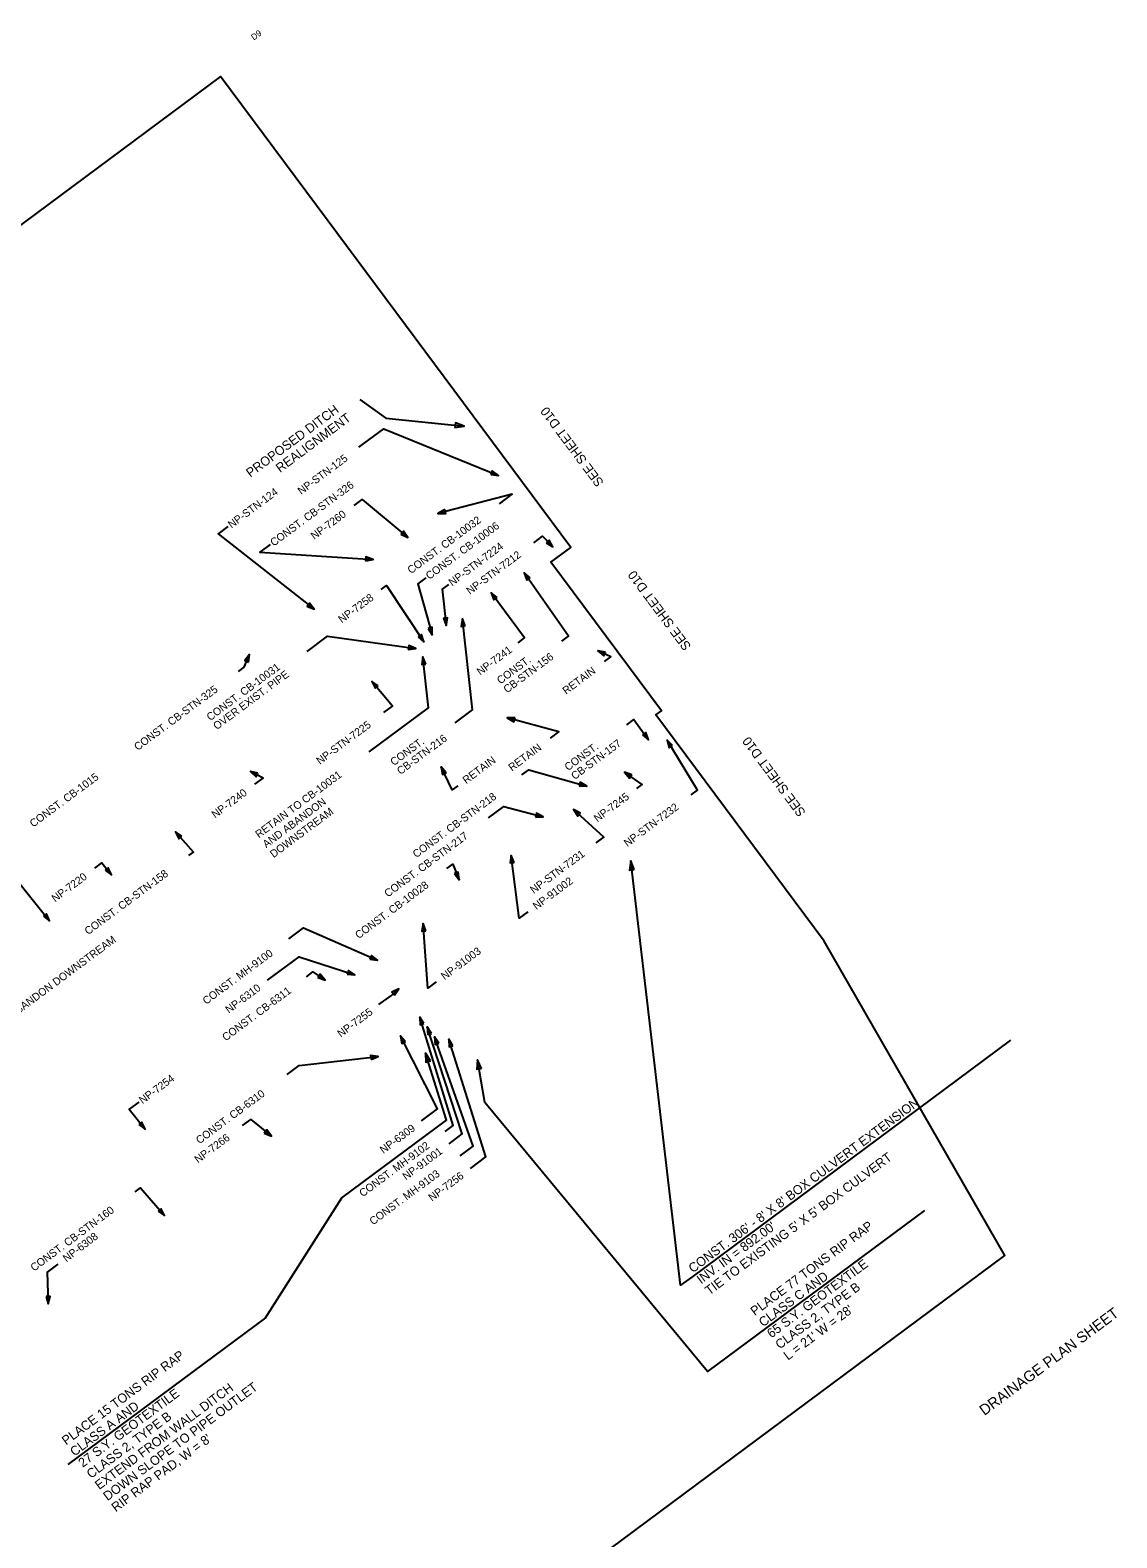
# Model space of a CAD drawing. Extents: x 1612334 to 1614149, y 1094755 to 1096548.
# Drawn here: x 1613444 to 1614149, y 1095569 to 1096548 of the extents above; entities that cross this region are included whole.
import ezdxf

# ---------------------------------------------------------------- set-up
doc = ezdxf.new("R2010")
doc.units = 0
for name, color, linetype in [('Level 13', 7, 'Continuous'), ('Level 15', 7, 'Continuous'), ('Level 9', 7, 'Continuous'), ('Node Storage', 7, 'Continuous'), ('RD_HY_DumbNodes', 7, 'Continuous')]:
    doc.layers.add(name, color=color, linetype=linetype)

msp = doc.modelspace()

# ---------------------------------------------------------------- linework, layer by layer
at = {"layer": 'Level 15'}
msp.add_lwpolyline([(1612485.6, 1095458.44), (1612588.44, 1095320.1), (1612593.04, 1095313.91), (1612580.15, 1095304.29), (1612634.52, 1095231.15), (1612645.51, 1095216.31), (1612653.41, 1095198.54), (1612742.51, 1095078.69), (1612867.99, 1094853.86), (1614076.24, 1095752.03), (1613959.14, 1095956.14), (1613849.89, 1096103.11), (1613853.42, 1096105.74), (1613781.72, 1096202.21), (1613794.63, 1096211.8), (1613636.52, 1096424.5), (1613567.38, 1096517.5), (1613431.61, 1096416.58), (1613412.2, 1096442.69), (1612334.44, 1095641.53)], close=True, dxfattribs=at)
msp.add_lwpolyline([(1612485.6, 1095458.44), (1612588.44, 1095320.1), (1612593.04, 1095313.91), (1612580.15, 1095304.29), (1612634.52, 1095231.15), (1612645.51, 1095216.31), (1612653.41, 1095198.54), (1612742.51, 1095078.69), (1612867.99, 1094853.86), (1614076.24, 1095752.03), (1613959.14, 1095956.14), (1613849.89, 1096103.11), (1613853.42, 1096105.74), (1613781.72, 1096202.21), (1613794.63, 1096211.8), (1613636.52, 1096424.5), (1613567.38, 1096517.5), (1613431.61, 1096416.58), (1613412.2, 1096442.69), (1612334.44, 1095641.53)], close=True, dxfattribs=at)
msp.add_lwpolyline([(1612485.6, 1095458.44), (1612588.44, 1095320.1), (1612593.04, 1095313.91), (1612580.15, 1095304.29), (1612634.52, 1095231.15), (1612645.51, 1095216.31), (1612653.41, 1095198.54), (1612742.51, 1095078.69), (1612867.99, 1094853.86), (1614076.24, 1095752.03), (1613959.14, 1095956.14), (1613849.89, 1096103.11), (1613853.42, 1096105.74), (1613781.72, 1096202.21), (1613794.63, 1096211.8), (1613636.52, 1096424.5), (1613567.38, 1096517.5), (1613431.61, 1096416.58), (1613412.2, 1096442.69), (1612334.44, 1095641.53)], close=True, dxfattribs=at)
msp.add_lwpolyline([(1612485.6, 1095458.44), (1612588.44, 1095320.1), (1612593.04, 1095313.91), (1612580.15, 1095304.29), (1612634.52, 1095231.15), (1612645.51, 1095216.31), (1612653.41, 1095198.54), (1612742.51, 1095078.69), (1612867.99, 1094853.86), (1614076.24, 1095752.03), (1613959.14, 1095956.14), (1613849.89, 1096103.11), (1613853.42, 1096105.74), (1613781.72, 1096202.21), (1613794.63, 1096211.8), (1613636.52, 1096424.5), (1613567.38, 1096517.5), (1613431.61, 1096416.58), (1613412.2, 1096442.69), (1612334.44, 1095641.53)], close=True, dxfattribs=at)
msp.add_lwpolyline([(1612485.6, 1095458.44), (1612588.44, 1095320.1), (1612593.04, 1095313.91), (1612580.15, 1095304.29), (1612634.52, 1095231.15), (1612645.51, 1095216.31), (1612653.41, 1095198.54), (1612742.51, 1095078.69), (1612867.99, 1094853.86), (1614076.24, 1095752.03), (1613959.14, 1095956.14), (1613849.89, 1096103.11), (1613853.42, 1096105.74), (1613781.72, 1096202.21), (1613794.63, 1096211.8), (1613636.52, 1096424.5), (1613567.38, 1096517.5), (1613431.61, 1096416.58), (1613412.2, 1096442.69), (1612334.44, 1095641.53)], close=True, dxfattribs=at)
msp.add_lwpolyline([(1612485.6, 1095458.44), (1612588.44, 1095320.1), (1612593.04, 1095313.91), (1612580.15, 1095304.29), (1612634.52, 1095231.15), (1612645.51, 1095216.31), (1612653.41, 1095198.54), (1612742.51, 1095078.69), (1612867.99, 1094853.86), (1614076.24, 1095752.03), (1613959.14, 1095956.14), (1613849.89, 1096103.11), (1613853.42, 1096105.74), (1613781.72, 1096202.21), (1613794.63, 1096211.8), (1613636.52, 1096424.5), (1613567.38, 1096517.5), (1613431.61, 1096416.58), (1613412.2, 1096442.69), (1612334.44, 1095641.53)], close=True, dxfattribs=at)
msp.add_lwpolyline([(1612485.6, 1095458.44), (1612588.44, 1095320.1), (1612593.04, 1095313.91), (1612580.15, 1095304.29), (1612634.52, 1095231.15), (1612645.51, 1095216.31), (1612653.41, 1095198.54), (1612742.51, 1095078.69), (1612867.99, 1094853.86), (1614076.24, 1095752.03), (1613959.14, 1095956.14), (1613849.89, 1096103.11), (1613853.42, 1096105.74), (1613781.72, 1096202.21), (1613794.63, 1096211.8), (1613636.52, 1096424.5), (1613567.38, 1096517.5), (1613431.61, 1096416.58), (1613412.2, 1096442.69), (1612334.44, 1095641.53)], close=True, dxfattribs=at)
msp.add_lwpolyline([(1612485.6, 1095458.44), (1612588.44, 1095320.1), (1612593.04, 1095313.91), (1612580.15, 1095304.29), (1612634.52, 1095231.15), (1612645.51, 1095216.31), (1612653.41, 1095198.54), (1612742.51, 1095078.69), (1612867.99, 1094853.86), (1614076.24, 1095752.03), (1613959.14, 1095956.14), (1613849.89, 1096103.11), (1613853.42, 1096105.74), (1613781.72, 1096202.21), (1613794.63, 1096211.8), (1613636.52, 1096424.5), (1613567.38, 1096517.5), (1613431.61, 1096416.58), (1613412.2, 1096442.69), (1612334.44, 1095641.53)], close=True, dxfattribs=at)
at = {"layer": 'RD_HY_DumbNodes'}
for p, q in [((1614080, 1095891.94), (1613873.1, 1095738.15)), ((1614024.06, 1095781.42), (1613915.13, 1095700.45)), ((1613596.48, 1095711.77), (1613468.24, 1095616.45))]:
    msp.add_line(p, q, dxfattribs=at)
for points in [[(1613657.71, 1096307.85), (1613674.6, 1096295.74), (1613725.35, 1096290.5)], [(1613657.18, 1096276.77), (1613673.38, 1096288.82), (1613747.68, 1096258.44)], [(1613654.01, 1096238.95), (1613659.32, 1096242.9), (1613688.88, 1096218.28)], [(1613748.34, 1096240.15), (1613756.61, 1096246.3), (1613708.44, 1096233.88)], [(1613572.19, 1096225.38), (1613565.78, 1096220.61), (1613628.01, 1096171.71)], [(1613599.6, 1096213.66), (1613592.87, 1096208.65), (1613666.29, 1096203.99)], [(1613770.62, 1096214.85), (1613776.37, 1096219.12), (1613782.99, 1096212.21)], [(1613700.53, 1096192.05), (1613695.4, 1096188.24), (1613704.71, 1096154.94)], [(1613788.77, 1096150.99), (1613793.05, 1096154.17), (1613764.43, 1096195.29)], [(1613671.56, 1096184.53), (1613675.04, 1096187.12), (1613699.37, 1096150.51)], [(1613715.37, 1096187.81), (1613711.22, 1096184.73), (1613713.76, 1096161.21)], [(1613760.4, 1096149.87), (1613764.62, 1096153.01), (1613742.87, 1096182.39)], [(1613719.66, 1096098.01), (1613730.79, 1096106.28), (1613724.3, 1096165.47)], [(1613623.5, 1096144.28), (1613636.83, 1096154.19), (1613694.04, 1096146.09)], [(1613816.53, 1096137.76), (1613820.53, 1096140.74), (1613812.23, 1096144.74)], [(1613578.94, 1096131.29), (1613582.65, 1096134.05), (1613586.21, 1096142.34)], [(1613663.77, 1096079.15), (1613702.21, 1096107.72), (1613698.7, 1096140.74)], [(1613673.27, 1096104.53), (1613679.01, 1096108.8), (1613665.49, 1096124.86)], [(1613781.4, 1096087.9), (1613786.94, 1096092.02), (1613753.43, 1096101.13)], [(1613831, 1096096.58), (1613835.59, 1096099.99), (1613845, 1096086.91)], [(1613872.83, 1096051.11), (1613876.95, 1096054.17), (1613857.11, 1096086.57)], [(1613589.71, 1096058.1), (1613595.03, 1096062.05), (1613586.78, 1096066.35)], [(1613721.25, 1096057.04), (1613717.62, 1096054.35), (1613710.51, 1096069.27)], [(1613762.94, 1096064.09), (1613767.31, 1096067.33), (1613805.02, 1096056.88)], [(1613837.42, 1096055.33), (1613840.94, 1096057.95), (1613829.48, 1096065.88)], [(1613741.29, 1096036.15), (1613751.18, 1096043.5), (1613776.71, 1096036.8)], [(1613811, 1096019.96), (1613816.05, 1096023.72), (1613796.42, 1096041.63)], [(1613546.77, 1096011.7), (1613549.86, 1096014), (1613538.11, 1096027.06)], [(1613485.89, 1096003.62), (1613490.41, 1096006.98), (1613496.5, 1095999.22)], [(1613714.22, 1096003.39), (1613718.07, 1096006.25), (1613722.25, 1095996.06)], [(1613766.84, 1095975.27), (1613761.17, 1095971.06), (1613755.96, 1096011.9)], [(1613873.1, 1095738.15), (1613865.87, 1095732.78), (1613833.55, 1096008.29)], [(1613428.12, 1095991.63), (1613434.7, 1095996.53), (1613456.39, 1095969.37)], [(1613707.26, 1095929.78), (1613701.84, 1095925.75), (1613698.85, 1095967.56)], [(1613611.57, 1095957.66), (1613621.21, 1095964.83), (1613669.26, 1095943.81)], [(1613597.84, 1095930.8), (1613618.43, 1095946.12), (1613654.53, 1095934.43)], [(1613623.12, 1095933.14), (1613627.3, 1095936.25), (1613635.2, 1095930.96)], [(1613670.16, 1095914.98), (1613678.24, 1095920.98), (1613682.98, 1095925.35)], [(1613713.07, 1095832.68), (1613718.33, 1095836.59), (1613696.7, 1095906.9)], [(1613715.71, 1095824.73), (1613724.17, 1095831.02), (1613701.51, 1095900.5)], [(1613697.76, 1095839.51), (1613708.16, 1095847.24), (1613684.06, 1095894.7)], [(1613722.93, 1095816.82), (1613731.25, 1095823.01), (1613706.25, 1095894.06)], [(1613729.46, 1095808.71), (1613739.52, 1095816.19), (1613715.42, 1095892.56)], [(1613596.48, 1095711.77), (1613645.98, 1095789.48), (1613714.05, 1095840.07), (1613700.41, 1095883.55)], [(1613610.6, 1095869.68), (1613618.33, 1095875.42), (1613669.69, 1095881.21)], [(1613915.13, 1095700.45), (1613883.42, 1095676.87), (1613738.81, 1095851.48), (1613734.2, 1095879.08)], [(1613514.44, 1095851.69), (1613508.15, 1095847.02), (1613518.38, 1095834.12)], [(1613581.67, 1095836.45), (1613586.98, 1095840.41), (1613600.32, 1095829.62)], [(1613512.01, 1095793.49), (1613515.35, 1095795.98), (1613530.96, 1095778.02)], [(1613461.88, 1095746.56), (1613454.94, 1095741.28), (1613455.56, 1095720.68)]]:
    msp.add_lwpolyline(points, dxfattribs=at)
for points in [[(1613719.43, 1096289.55), (1613725.35, 1096290.5), (1613719.75, 1096292.64)], [(1613742.72, 1096259.07), (1613747.68, 1096258.44), (1613743.7, 1096261.47)], [(1613712.79, 1096236.33), (1613708.44, 1096233.88), (1613713.44, 1096233.83)], [(1613684.35, 1096220.37), (1613688.88, 1096218.28), (1613686, 1096222.36)], [(1613778.72, 1096214.8), (1613782.99, 1096212.21), (1613780.58, 1096216.59)], [(1613661.38, 1096203.01), (1613666.29, 1096203.99), (1613661.55, 1096205.59)], [(1613768.25, 1096192.07), (1613764.43, 1096195.29), (1613766.12, 1096190.59)], [(1613746.79, 1096179.28), (1613742.87, 1096182.39), (1613744.71, 1096177.73)], [(1613623.41, 1096173.67), (1613628.01, 1096171.71), (1613625.01, 1096175.71)], [(1613711.95, 1096165.87), (1613713.76, 1096161.21), (1613714.53, 1096166.15)], [(1613726.11, 1096160.81), (1613724.3, 1096165.47), (1613723.54, 1096160.52)], [(1613695.62, 1096153.82), (1613699.37, 1096150.51), (1613697.78, 1096155.25)], [(1613702.16, 1096159.25), (1613704.71, 1096154.94), (1613704.65, 1096159.94)], [(1613689.08, 1096145.48), (1613694.04, 1096146.09), (1613689.44, 1096148.05)], [(1613817.14, 1096143.81), (1613812.23, 1096144.74), (1613816.02, 1096141.48)], [(1613585.5, 1096137.4), (1613586.21, 1096142.34), (1613583.12, 1096138.42)], [(1613700.5, 1096136.08), (1613698.7, 1096140.74), (1613697.92, 1096135.8)], [(1613669.59, 1096122), (1613665.49, 1096124.86), (1613667.61, 1096120.33)], [(1613758.43, 1096101.12), (1613753.43, 1096101.13), (1613757.75, 1096098.62)], [(1613841.13, 1096090.08), (1613845, 1096086.91), (1613843.23, 1096091.59)], [(1613860.73, 1096083.12), (1613857.11, 1096086.57), (1613858.52, 1096081.77)], [(1613591.66, 1096065.27), (1613586.78, 1096066.35), (1613590.46, 1096062.97)], [(1613713.75, 1096065.46), (1613710.51, 1096069.27), (1613711.42, 1096064.35)], [(1613834.19, 1096064.2), (1613829.48, 1096065.88), (1613832.72, 1096062.07)], [(1613800.02, 1096056.92), (1613805.02, 1096056.88), (1613800.71, 1096059.42)], [(1613771.71, 1096036.78), (1613776.71, 1096036.8), (1613772.36, 1096039.28)], [(1613800.86, 1096039.33), (1613796.42, 1096041.63), (1613799.12, 1096037.42)], [(1613542.3, 1096024.33), (1613538.11, 1096027.06), (1613540.38, 1096022.6)], [(1613757.85, 1096007.28), (1613755.96, 1096011.9), (1613755.29, 1096006.95)], [(1613835.77, 1096002.71), (1613833.55, 1096008.29), (1613832.69, 1096002.35)], [(1613492.5, 1096002.22), (1613496.5, 1095999.22), (1613494.54, 1096003.81)], [(1613719.22, 1096000.04), (1613722.25, 1095996.06), (1613721.61, 1096001.02)], [(1613452.37, 1095972.33), (1613456.39, 1095969.37), (1613454.39, 1095973.95)], [(1613700.48, 1095962.84), (1613698.85, 1095967.56), (1613697.9, 1095962.65)], [(1613664.31, 1095944.56), (1613669.26, 1095943.81), (1613665.35, 1095946.93)], [(1613649.54, 1095934.68), (1613654.53, 1095934.43), (1613650.34, 1095937.14)], [(1613630.47, 1095932.57), (1613635.2, 1095930.96), (1613631.91, 1095934.72)], [(1613680.31, 1095921.13), (1613682.98, 1095925.35), (1613678.55, 1095923.03)], [(1613699.36, 1095902.66), (1613696.7, 1095906.9), (1613696.88, 1095901.9)], [(1613704.24, 1095896.31), (1613701.51, 1095900.5), (1613701.78, 1095895.51)], [(1613687.4, 1095890.98), (1613684.06, 1095894.7), (1613685.1, 1095889.81)], [(1613709.07, 1095889.93), (1613706.25, 1095894.06), (1613706.63, 1095889.07)], [(1613718.11, 1095888.34), (1613715.42, 1095892.56), (1613715.64, 1095887.56)], [(1613665.04, 1095879.38), (1613669.69, 1095881.21), (1613664.75, 1095881.96)], [(1613703.62, 1095878.48), (1613700.41, 1095883.55), (1613700.66, 1095877.55)], [(1613736.69, 1095873.62), (1613734.2, 1095879.08), (1613733.62, 1095873.11)], [(1613514.36, 1095837.1), (1613518.38, 1095834.12), (1613516.39, 1095838.71)], [(1613595.75, 1095831.65), (1613600.32, 1095829.62), (1613597.38, 1095833.66)], [(1613526.81, 1095780.82), (1613530.96, 1095778.02), (1613528.77, 1095782.52)], [(1613454.12, 1095725.47), (1613455.56, 1095720.68), (1613456.71, 1095725.54)]]:
    msp.add_lwpolyline(points, close=True, dxfattribs=at)

# ---------------------------------------------------------------- texts
at = {"layer": 'Level 13'}
for p in [(1613816.33, 1096253.99), (1613873.03, 1096147.7), (1613947.35, 1096039.81)]:
    msp.add_text('SEE SHEET D10', height=6, rotation=126.67686, dxfattribs=at).set_placement(p)
at = {"layer": 'Level 9'}
msp.add_text('D9', height=4, rotation=36.62559, dxfattribs=at).set_placement((1613588.95, 1096540.78))
at = {"layer": 'Node Storage'}
msp.add_text('DRAINAGE PLAN SHEET', height=6.9833, rotation=36.62559, dxfattribs=at).set_placement((1614063.02, 1095647.9))
at = {"layer": 'RD_HY_DumbNodes'}
for s, height, rotation, p in [('PROPOSED DITCH', 6, 36.62397, (1613586.72, 1096256.95)), ('REALIGNMENT', 6, 36.62397, (1613606.01, 1096260.07)), ('NP-STN-125', 5, 36.62397, (1613619.7, 1096245.8)), ('NP-STN-124', 5, 36.62397, (1613574.48, 1096223.97)), ('CONST. CB-STN-326', 5, 36.62397, (1613601.9, 1096212.25)), ('NP-7260', 5, 36.62397, (1613628.16, 1096216.61)), ('CONST. CB-10032', 5, 36.62397, (1613690.95, 1096194.38)), ('CONST. CB-10006', 5, 36.62397, (1613702.83, 1096190.64)), ('NP-STN-7224', 5, 36.62397, (1613717.66, 1096186.4)), ('NP-STN-7212', 5, 36.62397, (1613729.16, 1096180.92)), ('NP-7258', 5, 36.62397, (1613646.02, 1096162.44)), ('NP-7241', 5, 36.62397, (1613735.88, 1096128.53)), ('CB-STN-156', 5, 36.62397, (1613753.25, 1096116.98)), ('CONST. CB-10031', 5, 36.62397, (1613560.62, 1096098.92)), ('CONST.', 5, 36.62397, (1613748.95, 1096122.76)), ('RETAIN', 5, 36.62397, (1613791.57, 1096116.09)), ('OVER EXIST. PIPE', 5, 36.62397, (1613564.92, 1096093.13)), ('CONST. CB-STN-325', 5, 36.62397, (1613513.59, 1096079.6)), ('NP-STN-7225', 5, 36.62397, (1613631.81, 1096070.6)), ('CONST.', 5, 36.62397, (1613679.84, 1096069.78)), ('CB-STN-216', 5, 36.62397, (1613684.14, 1096064)), ('RETAIN', 5, 36.62397, (1613756.44, 1096066.24)), ('CONST.', 5, 36.62397, (1613792.86, 1096066.49)), ('CB-STN-157', 5, 36.62397, (1613797.16, 1096060.71)), ('RETAIN', 5, 36.62397, (1613726.75, 1096058.02)), ('CONST. CB-1015', 5, 36.62397, (1613445.84, 1096029.83)), ('RETAIN TO CB-10031', 5, 36.62397, (1613592.24, 1096022.86)), ('NP-7240', 5, 36.62397, (1613563.85, 1096035.77)), ('AND ABANDON', 5, 36.62397, (1613597.01, 1096016.44)), ('CONST. CB-STN-218', 5, 36.62397, (1613694.38, 1096010.01)), ('NP-7245', 5, 36.62397, (1613811.88, 1096033.24)), ('NP-STN-7232', 5, 36.62397, (1613831.37, 1096017.17)), ('DOWNSTREAM', 5, 36.62397, (1613601.78, 1096010.02)), ('CONST. CB-STN-217', 5, 36.62397, (1613675.94, 1095984.46)), ('NP-STN-7231', 5, 36.62397, (1613770.55, 1095986.78)), ('NP-7220', 5, 36.62397, (1613460.04, 1095981.29)), ('CONST. CB-STN-158', 5, 36.62397, (1613481.42, 1095960.01)), ('NP-91002', 5, 36.62397, (1613772.35, 1095976.25)), ('CONST. CB-10028', 5, 36.62397, (1613656.98, 1095957.43)), ('RETAIN AND SLIP LINE TO MH-907 ABANDON DOWNSTREAM', 5, 36.62397, (1613342.6, 1095839.09)), ('CONST. MH-9100', 5, 36.62397, (1613558.04, 1095914.75)), ('NP-91003', 5, 36.62397, (1613712.76, 1095930.75)), ('NP-6310', 5, 36.62397, (1613572.78, 1095909.07)), ('CONST. CB-6311', 5, 36.62397, (1613570.73, 1095891.08)), ('NP-7255', 5, 36.62397, (1613645.43, 1095893.48)), ('NP-7254', 5, 36.62397, (1613516.74, 1095850.28)), ('CONST. CB-6310', 5, 36.62397, (1613553.67, 1095824.24)), ("CONST. 306' - 8' X 8' BOX CULVERT EXTENSION", 6, 36.62397, (1613873.81, 1095740.55)), ('NP-7266', 5, 36.63995, (1613552.74, 1095811.82)), ('NP-6309', 5, 36.62397, (1613673.03, 1095818.01)), ('CONST. MH-9102', 5, 36.62397, (1613659.66, 1095789.87)), ('NP-91001', 5, 36.62397, (1613687.71, 1095800.81)), ("TIE TO EXISTING 5' X 5' BOX CULVERT", 6, 36.62397, (1613884.55, 1095726.1)), ('CONST. MH-9103', 5, 36.62397, (1613666.31, 1095771.62)), ('NP-7256', 5, 36.62397, (1613704.53, 1095787.06)), ('CONST. CB-STN-160', 5, 36.62397, (1613446.34, 1095741.57)), ("INV. IN = 892.00' ", 6, 36.62397, (1613879.18, 1095733.33)), ('PLACE 77 TONS RIP RAP', 6, 36.62559, (1613914.04, 1095712.72)), ('NP-6308', 5, 37.26732, (1613467.38, 1095747.6)), ('65 S.Y. GEOTEXTILE', 6, 36.62559, (1613924.78, 1095698.28)), ('CLASS C AND', 6, 36.62559, (1613919.41, 1095705.5)), ('CLASS 2, TYPE B', 6, 36.62559, (1613930.15, 1095691.05)), ("L = 21' W = 28'", 6, 36.62559, (1613935.52, 1095683.83)), ('PLACE 15 TONS RIP RAP', 6, 36.62559, (1613467.16, 1095628.73)), ('27 S.Y. GEOTEXTILE', 6, 36.62559, (1613477.9, 1095614.28)), ('EXTEND FROM WALL DITCH', 6, 36.62559, (1613488.63, 1095599.83)), ('DOWN SLOPE TO PIPE OUTLET', 6, 36.62559, (1613494, 1095592.61)), ('CLASS A AND', 6, 36.62559, (1613472.53, 1095621.5)), ('CLASS 2, TYPE B', 6, 36.62559, (1613483.26, 1095607.06)), ("RIP RAP PAD, W = 8'", 6, 36.62559, (1613499.37, 1095585.39))]:
    msp.add_text(s, height=height, rotation=rotation, dxfattribs=at).set_placement(p)

doc.saveas('drawing.dxf')
